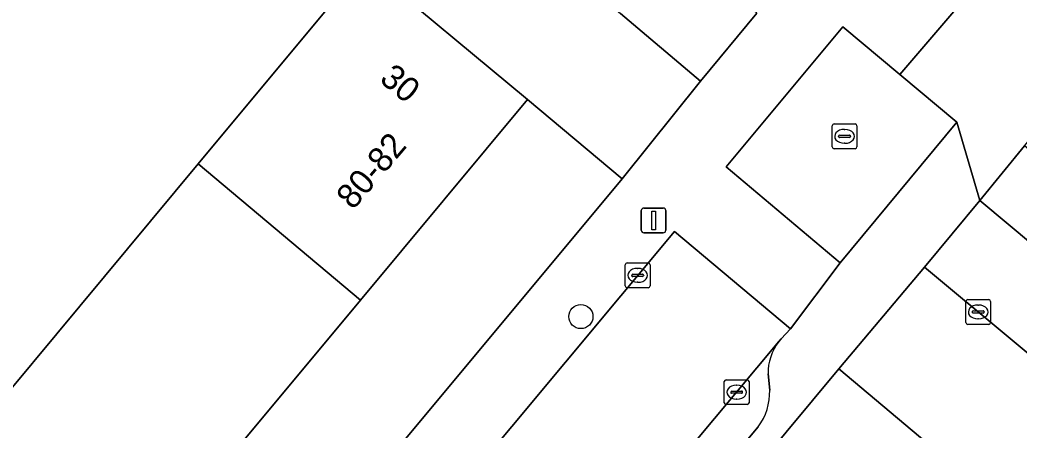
# Model space of a CAD drawing. Extents: x 162523 to 163266, y 381230 to 382050.
# Drawn here: x 162914.22 to 162954.65, y 381606.94 to 381623.52 of the extents above; entities that cross this region are included whole.
import ezdxf

# ---------------------------------------------------------------- set-up
doc = ezdxf.new("R2010")
doc.units = 0
for name, color, linetype in [('IMGEO_Boom', 7, 'Continuous'), ('IMGEO_Erf', 7, 'Continuous'), ('IMGEO_Groenvoorziening', 7, 'Continuous'), ('IMGEO_Kolk', 7, 'Continuous'), ('IMGEO_Lichtmast', 7, 'Continuous'), ('IMGEO_Pand', 7, 'Continuous'), ('IMGEO_Pand_nummerreeks', 7, 'Continuous'), ('IMGEO_Parkeervlak_open', 7, 'Continuous'), ('IMGEO_Rijbaan_lokaal_open', 7, 'Continuous'), ('IMGEO_Rioolput', 7, 'Continuous'), ('IMGEO_Voetpad_open', 7, 'Continuous')]:
    doc.layers.add(name, color=color, linetype=linetype)

msp = doc.modelspace()

# ---------------------------------------------------------------- linework, layer by layer
at = {"layer": 'IMGEO_Boom'}
msp.add_circle((162936.894, 381611.526), 0.489, dxfattribs=at)
at = {"layer": 'IMGEO_Erf'}
for points in [[(162921.421, 381617.708), (162928.147, 381625.792), (162921.065, 381631.586), (162916.591, 381635.339), (162914.907, 381633.298), (162919.111, 381629.771), (162916.823, 381626.999), (162912.619, 381630.526), (162908.685, 381625.959), (162890.582, 381603.997), (162889.874, 381603.227), (162901.376, 381593.615), (162908.05, 381601.637)], [(162911.768, 381584.95), (162938.568, 381617.099), (162934.732, 381620.307), (162927.977, 381612.195), (162914.597, 381596.129), (162907.946, 381588.143)]]:
    msp.add_lwpolyline(points, close=True, dxfattribs=at)
at = {"layer": 'IMGEO_Groenvoorziening'}
msp.add_lwpolyline([(162938.764, 381590.661), (162951.476, 381605.922), (162947.33, 381609.407), (162934.619, 381594.127)], close=True, dxfattribs=at)
at = {"layer": 'IMGEO_Kolk'}
for p, q in [((162938.69, 381612.768), (162938.69, 381613.62)), ((162938.765, 381613.694), (162939.617, 381613.694)), ((162939.178, 381613.474), (162939.203, 381613.474)), ((162939.691, 381613.62), (162939.691, 381612.768)), ((162938.949, 381613.188), (162938.949, 381613.2)), ((162939.387, 381613.151), (162938.989, 381613.151)), ((162938.992, 381613.237), (162939.39, 381613.237)), ((162939.433, 381613.2), (162939.433, 381613.188)), ((162939.617, 381612.694), (162938.765, 381612.694)), ((162939.201, 381612.914), (162939.176, 381612.914)), ((162952.536, 381612.212), (162953.388, 381612.212)), ((162952.461, 381611.286), (162952.461, 381612.138)), ((162952.949, 381611.992), (162952.974, 381611.992)), ((162953.462, 381612.138), (162953.462, 381611.286)), ((162952.72, 381611.706), (162952.72, 381611.718)), ((162953.158, 381611.669), (162952.76, 381611.669)), ((162952.763, 381611.755), (162953.161, 381611.755)), ((162952.972, 381611.432), (162952.947, 381611.432)), ((162953.204, 381611.718), (162953.204, 381611.706)), ((162953.388, 381611.212), (162952.536, 381611.212)), ((162942.767, 381608.969), (162943.619, 381608.969)), ((162942.692, 381608.043), (162942.692, 381608.895)), ((162943.18, 381608.749), (162943.205, 381608.749)), ((162943.693, 381608.895), (162943.693, 381608.043)), ((162942.951, 381608.463), (162942.951, 381608.475)), ((162943.389, 381608.426), (162942.991, 381608.426)), ((162942.994, 381608.512), (162943.392, 381608.512)), ((162943.203, 381608.189), (162943.178, 381608.189)), ((162943.435, 381608.475), (162943.435, 381608.463)), ((162943.619, 381607.969), (162942.767, 381607.969))]:
    msp.add_line(p, q, dxfattribs=at)
for points in [[(162938.69, 381612.768), (162938.69, 381613.62)], [(162938.765, 381613.694), (162939.617, 381613.694)], [(162939.691, 381613.62), (162939.691, 381612.768)], [(162939.617, 381612.694), (162938.765, 381612.694)], [(162952.536, 381612.212), (162953.388, 381612.212)], [(162952.461, 381611.286), (162952.461, 381612.138)], [(162953.462, 381612.138), (162953.462, 381611.286)], [(162953.388, 381611.212), (162952.536, 381611.212)], [(162942.767, 381608.969), (162943.619, 381608.969)], [(162942.692, 381608.043), (162942.692, 381608.895)], [(162943.693, 381608.895), (162943.693, 381608.043)], [(162943.619, 381607.969), (162942.767, 381607.969)]]:
    msp.add_lwpolyline(points, dxfattribs=at)
for centre, radius, start, end in [((162938.767, 381613.618), 0.0765, 91.552, 178.448), ((162938.767, 381613.618), 0.0765, 91.552, 178.448), ((162939.615, 381613.618), 0.0765, 1.552, 88.448), ((162939.615, 381613.618), 0.0765, 1.552, 88.448), ((162938.989, 381613.197), 0.0403, 85.8775, 175.7526), ((162938.986, 381613.187), 0.0366, 178.938, 274.7102), ((162939.39, 381613.194), 0.043, 264.8664, 352.4533), ((162939.394, 381613.199), 0.0386, 1.7309, 96.639), ((162938.767, 381612.77), 0.0765, 181.552, 268.448), ((162938.767, 381612.77), 0.0765, 181.552, 268.448), ((162939.615, 381612.77), 0.0765, 271.552, 358.448), ((162939.615, 381612.77), 0.0765, 271.552, 358.448), ((162952.538, 381612.136), 0.0765, 91.552, 178.448), ((162952.538, 381612.136), 0.0765, 91.552, 178.448), ((162953.386, 381612.136), 0.0765, 1.552, 88.448), ((162953.386, 381612.136), 0.0765, 1.552, 88.448), ((162952.76, 381611.715), 0.0403, 85.8775, 175.7526), ((162952.757, 381611.705), 0.0366, 178.938, 274.7102), ((162953.161, 381611.712), 0.043, 264.8664, 352.4533), ((162953.165, 381611.717), 0.0386, 1.7309, 96.639), ((162952.538, 381611.288), 0.0765, 181.552, 268.448), ((162952.538, 381611.288), 0.0765, 181.552, 268.448), ((162953.386, 381611.288), 0.0765, 271.552, 358.448), ((162953.386, 381611.288), 0.0765, 271.552, 358.448), ((162942.769, 381608.893), 0.0765, 91.552, 178.448), ((162942.769, 381608.893), 0.0765, 91.552, 178.448), ((162943.617, 381608.893), 0.0765, 1.552, 88.448), ((162943.617, 381608.893), 0.0765, 1.552, 88.448), ((162942.991, 381608.472), 0.0403, 85.8775, 175.7526), ((162942.988, 381608.462), 0.0366, 178.938, 274.7102), ((162943.392, 381608.469), 0.043, 264.8664, 352.4533), ((162943.396, 381608.474), 0.0386, 1.7309, 96.639), ((162942.769, 381608.045), 0.0765, 181.552, 268.448), ((162942.769, 381608.045), 0.0765, 181.552, 268.448), ((162943.617, 381608.045), 0.0765, 271.552, 358.448), ((162943.617, 381608.045), 0.0765, 271.552, 358.448)]:
    msp.add_arc(centre, radius, start, end, dxfattribs=at)
for centre, major_axis, ratio, start_param, end_param in [((162939.177, 381613.194), (-0.387, 0.002), 0.722429, 4.712389, 7.853982), ((162939.202, 381613.194), (-0.39, 0.002), 0.717154, 1.570796, 4.712389), ((162952.948, 381611.712), (-0.387, 0.002), 0.722429, 4.712389, 7.853982), ((162952.973, 381611.712), (-0.39, 0.002), 0.717154, 1.570796, 4.712389), ((162943.179, 381608.469), (-0.387, 0.002), 0.722429, 4.712389, 7.853982), ((162943.204, 381608.469), (-0.39, 0.002), 0.717154, 1.570796, 4.712389)]:
    msp.add_ellipse(centre, major_axis=major_axis, ratio=ratio, start_param=start_param, end_param=end_param, dxfattribs=at)
at = {"layer": 'IMGEO_Lichtmast'}
for p, q in [((162939.438, 381615.915), (162940.228, 381615.915)), ((162940.228, 381615.915), (162939.438, 381615.915)), ((162939.338, 381615.015), (162939.338, 381615.815)), ((162939.338, 381615.815), (162939.338, 381615.015)), ((162940.328, 381615.815), (162940.328, 381615.015)), ((162940.328, 381615.015), (162940.328, 381615.815)), ((162940.228, 381614.915), (162939.438, 381614.915)), ((162939.438, 381614.915), (162940.228, 381614.915))]:
    msp.add_line(p, q, dxfattribs=at)
msp.add_lwpolyline([(162939.758, 381615.79), (162939.908, 381615.79), (162939.908, 381615.04), (162939.758, 381615.04), (162939.758, 381615.79)], dxfattribs=at)
for centre, start, end in [((162939.438, 381615.815), 90, 180), ((162939.438, 381615.815), 90, 180), ((162940.228, 381615.815), 0, 90), ((162940.228, 381615.815), 360, 90), ((162939.438, 381615.015), 180, 270), ((162939.438, 381615.015), 180, 270), ((162940.228, 381615.015), 270, 0), ((162940.228, 381615.015), 270, 0)]:
    msp.add_arc(centre, 0.1, start, end, dxfattribs=at)
at = {"layer": 'IMGEO_Pand'}
for points in [[(162927.977, 381612.195), (162934.732, 381620.307), (162928.147, 381625.792), (162921.421, 381617.708)], [(162908.05, 381601.637), (162914.597, 381596.129), (162927.977, 381612.195), (162921.421, 381617.708)]]:
    msp.add_lwpolyline(points, close=True, dxfattribs=at)
at = {"layer": 'IMGEO_Parkeervlak_open'}
for points in [[(162944.899, 381610.512), (162919.507, 381580.127)], [(162944.53, 381608.551), (162944.463, 381609.205)], [(162922.876, 381581.693), (162944.063, 381607.062)]]:
    msp.add_lwpolyline(points, dxfattribs=at)
for centre, radius, start, end in [((162946.531, 381609.241), 2.068, 142.0945, 181.0093), ((162942.135, 381608.484), 2.396, 323.5804, 1.5932)]:
    msp.add_arc(centre, radius, start, end, dxfattribs=at)
at = {"layer": 'IMGEO_Rijbaan_lokaal_open'}
msp.add_lwpolyline([(162922.11, 381637.169), (162923.792, 381636.009), (162924.592, 381635.395), (162925.718, 381634.445), (162928.612, 381632.057), (162929.391, 381631.408), (162938.502, 381623.781), (162941.732, 381621.049), (162944.009, 381623.798), (162943.706, 381624.046), (162943.398, 381624.302), (162925.045, 381639.55), (162922.663, 381641.401), (162921.894, 381642.081), (162921.134, 381642.861), (162916.129, 381647.892), (162913.528, 381645.291), (162919.687, 381639.115)], dxfattribs=at)
for points in [[(162952.1, 381619.384), (162949.795, 381621.313), (162947.489, 381623.243), (162942.764, 381617.575), (162945.072, 381615.639), (162947.38, 381613.702)], [(162995.604, 381578.864), (162980.91, 381591.262), (162978.815, 381594.719), (162959.497, 381610.819), (162953.023, 381616.223), (162950.782, 381613.529), (162957.551, 381607.889), (162961.614, 381604.504), (162975.34, 381593.036), (162978.6, 381587.852), (162992.932, 381575.733)], [(162940.674, 381614.971), (162914.303, 381583.342), (162916.611, 381581.371), (162918.918, 381579.401), (162919.507, 381580.127), (162944.899, 381610.512), (162944.997, 381610.63), (162945.369, 381611.032), (162943.022, 381613.001)]]:
    msp.add_lwpolyline(points, close=True, dxfattribs=at)
at = {"layer": 'IMGEO_Rioolput'}
for p, q in [((162947.056, 381618.388), (162947.056, 381619.24)), ((162947.131, 381619.314), (162947.983, 381619.314)), ((162947.544, 381619.094), (162947.569, 381619.094)), ((162948.057, 381619.24), (162948.057, 381618.388)), ((162947.315, 381618.808), (162947.315, 381618.82)), ((162947.753, 381618.771), (162947.355, 381618.771)), ((162947.358, 381618.857), (162947.756, 381618.857)), ((162947.799, 381618.82), (162947.799, 381618.808)), ((162947.983, 381618.314), (162947.131, 381618.314)), ((162947.567, 381618.534), (162947.542, 381618.534))]:
    msp.add_line(p, q, dxfattribs=at)
for points in [[(162947.056, 381618.388), (162947.056, 381619.24)], [(162947.131, 381619.314), (162947.983, 381619.314)], [(162948.057, 381619.24), (162948.057, 381618.388)], [(162947.983, 381618.314), (162947.131, 381618.314)]]:
    msp.add_lwpolyline(points, dxfattribs=at)
for centre, radius, start, end in [((162947.133, 381619.238), 0.0765, 91.552, 178.448), ((162947.133, 381619.238), 0.0765, 91.552, 178.448), ((162947.981, 381619.238), 0.0765, 1.552, 88.448), ((162947.981, 381619.238), 0.0765, 1.552, 88.448), ((162947.355, 381618.817), 0.0403, 85.8775, 175.7526), ((162947.352, 381618.807), 0.0366, 178.938, 274.7102), ((162947.756, 381618.814), 0.043, 264.8664, 352.4533), ((162947.76, 381618.819), 0.0386, 1.7309, 96.639), ((162947.133, 381618.39), 0.0765, 181.552, 268.448), ((162947.133, 381618.39), 0.0765, 181.552, 268.448), ((162947.981, 381618.39), 0.0765, 271.552, 358.448), ((162947.981, 381618.39), 0.0765, 271.552, 358.448)]:
    msp.add_arc(centre, radius, start, end, dxfattribs=at)
for centre, major_axis, ratio, start_param, end_param in [((162947.543, 381618.814), (-0.387, 0.002), 0.722429, 4.712389, 7.853982), ((162947.568, 381618.814), (-0.39, 0.002), 0.717154, 1.570796, 4.712389)]:
    msp.add_ellipse(centre, major_axis=major_axis, ratio=ratio, start_param=start_param, end_param=end_param, dxfattribs=at)
at = {"layer": 'IMGEO_Voetpad_open'}
for points in [[(162862.821, 381717.136), (162859.084, 381716.26), (162859.316, 381715.205), (162862.283, 381703.406), (162863.706, 381697.45), (162864.542, 381694.268), (162878.048, 381675.26), (162879.384, 381673.963), (162879.464, 381673.885), (162916.21, 381636.979), (162915.574, 381636.334), (162916.591, 381635.339), (162921.065, 381631.586), (162928.147, 381625.792), (162934.732, 381620.307), (162938.568, 381617.099), (162941.732, 381621.049), (162938.502, 381623.781)], [(162944.009, 381623.798), (162941.732, 381621.049), (162938.568, 381617.099), (162911.768, 381584.95), (162907.601, 381579.919), (162905.609, 381577.531), (162907.106, 381574.604), (162912.426, 381580.96), (162914.72, 381579.007), (162917.013, 381577.055), (162918.918, 381579.401), (162916.611, 381581.371), (162914.303, 381583.342), (162940.674, 381614.971), (162943.022, 381613.001), (162945.369, 381611.032), (162947.38, 381613.702), (162945.072, 381615.639), (162942.764, 381617.575), (162947.489, 381623.243), (162949.795, 381621.313), (162954.316, 381626.612)], [(162957.121, 381625.277), (162956.912, 381625.027), (162956.624, 381624.669), (162954.316, 381626.612), (162949.795, 381621.313), (162952.1, 381619.384), (162953.023, 381616.223), (162954.837, 381618.426), (162957.284, 381621.356), (162958.942, 381623.327)], [(162920.788, 381577.63), (162933.64, 381592.954), (162934.619, 381594.127), (162947.33, 381609.407), (162950.782, 381613.529), (162953.023, 381616.223), (162952.1, 381619.384), (162947.38, 381613.702), (162945.369, 381611.032), (162944.997, 381610.63), (162944.899, 381610.512)], [(163000, 381579.765), (162981.863, 381595.134), (162984.611, 381598.375), (162986.061, 381600.085), (162983.414, 381602.297), (162971.989, 381611.847), (162965.42, 381617.32), (162964.065, 381615.701), (162983.082, 381599.812), (162980.589, 381596.946), (162961.61, 381612.777), (162958.958, 381614.986), (162954.837, 381618.426), (162953.023, 381616.223), (162959.497, 381610.819)], [(162961.614, 381604.504), (162957.551, 381607.889), (162950.782, 381613.529), (162947.33, 381609.407), (162951.476, 381605.922), (162954.285, 381603.956), (162960.864, 381598.479), (162972.364, 381588.856), (162972.378, 381588.844), (162974.491, 381587.076), (162974.802, 381586.815), (162975.401, 381587.503), (163030.105, 381541.182), (163029.277, 381540.181), (163030.403, 381539.234), (163034.957, 381535.373), (163039.544, 381531.596), (163040.696, 381530.636), (163046.221, 381525.516), (163049.858, 381522.146), (163052.364, 381524.823)], [(162944.463, 381609.205), (162944.53, 381608.551)], [(162944.063, 381607.062), (162922.876, 381581.693)]]:
    msp.add_lwpolyline(points, dxfattribs=at)
for centre, radius, start, end in [((162946.531, 381609.241), 2.068, 142.0945, 181.0093), ((162942.135, 381608.484), 2.396, 323.5804, 1.5932)]:
    msp.add_arc(centre, radius, start, end, dxfattribs=at)

# ---------------------------------------------------------------- texts
at = {"layer": 'IMGEO_Pand_nummerreeks'}
for s, rotation, p in [('30', 320.2073, (162928.707, 381621.056)), ('80-82', 49.6701, (162927.683, 381615.806))]:
    msp.add_text(s, height=1, rotation=rotation, dxfattribs=at).set_placement(p)

doc.saveas('drawing.dxf')
